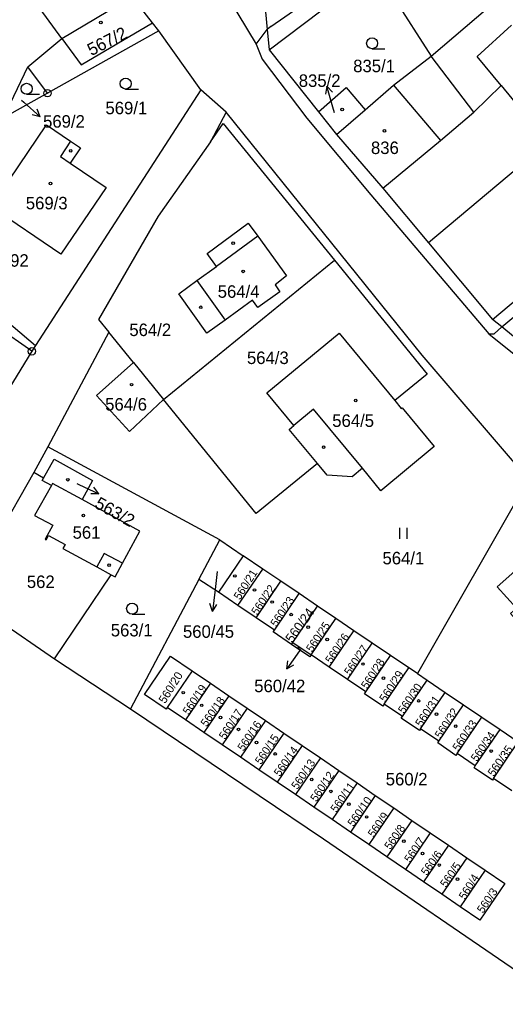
# Model space of a CAD drawing. Extents: x -776606 to -776076, y -974328 to -973875.
# Drawn here: x -776336.7 to -776270.5, y -974129.8 to -973997.7 of the extents above; entities that cross this region are included whole.
import ezdxf

# ---------------------------------------------------------------- set-up
doc = ezdxf.new("R2010")
doc.units = 0
for name, color, linetype in [('Hranice parcel', 7, 'Continuous'), ('Parcelní čísla', 7, 'Continuous'), ('Pop  PČ popisy', 7, 'Continuous'), ('Vnitřní kresba', 7, 'Continuous'), ('Značky bodu BP', 7, 'Continuous'), ('Značky budov', 7, 'Continuous'), ('Značky kultur', 7, 'Continuous')]:
    doc.layers.add(name, color=color, linetype=linetype)

msp = doc.modelspace()

# ---------------------------------------------------------------- linework, layer by layer
at = {"layer": 'Hranice parcel'}
for p, q in [((-776302.67, -974001.86), (-776288.2, -973990.91)), ((-776288.2, -973990.91), (-776280.61, -974002.73)), ((-776330.9, -974000.3), (-776321.3, -973994.6)), ((-776280.61, -974002.73), (-776271.38, -973994.77)), ((-776317.7, -973999.3), (-776332.85, -974007.77)), ((-776311.96, -974007.29), (-776317.7, -973999.3)), ((-776335.5, -974004.17), (-776330.9, -974000.3)), ((-776302.67, -974001.86), (-776295.97, -974010.29)), ((-776274.81, -974010.35), (-776280.61, -974002.73)), ((-776338.84, -974011.12), (-776335.5, -974004.17)), ((-776332.85, -974007.77), (-776335.5, -974004.17)), ((-776311.96, -974007.29), (-776334.46, -974042.11)), ((-776308.52, -974010.36), (-776311.96, -974007.29)), ((-776332.85, -974007.77), (-776338.84, -974011.12)), ((-776293.49, -974013.38), (-776289.58, -974010.03)), ((-776308.52, -974010.36), (-776310.67, -974014.4)), ((-776295.97, -974010.29), (-776293.49, -974013.38)), ((-776293.49, -974013.38), (-776287.2, -974020.7)), ((-776272.25, -974038.56), (-776255.71, -974024.55)), ((-776348.16, -974030.54), (-776334.46, -974042.11)), ((-776317.05, -974049.45), (-776293.78, -974030.52)), ((-776334.96, -974042.91), (-776348.94, -974033.12)), ((-776324.49, -974040.31), (-776332.81, -974055.91)), ((-776321.13, -974044.44), (-776324.49, -974040.31)), ((-776334.96, -974042.91), (-776338.11, -974048.02)), ((-776334.46, -974042.11), (-776334.96, -974042.91)), ((-776321.13, -974044.44), (-776317.05, -974049.45)), ((-776317.05, -974049.45), (-776321.68, -974053.83)), ((-776296.1, -974058.19), (-776299.93, -974053.54)), ((-776332.81, -974055.91), (-776334.7, -974059.4)), ((-776309.4, -974068.57), (-776332.81, -974055.91)), ((-776294.79, -974059.76), (-776296.1, -974058.19)), ((-776334.7, -974059.4), (-776344.3, -974076.22)), ((-776333.4, -974060.17), (-776334.7, -974059.4)), ((-776267.37, -974060.3), (-776282.47, -974086.79)), ((-776312.25, -974073.99), (-776309.4, -974068.57)), ((-776309.4, -974068.57), (-776306.21, -974070.73)), ((-776306.21, -974070.73), (-776309.57, -974075.7)), ((-776303.54, -974072.58), (-776306.21, -974070.73)), ((-776331.9, -974084.75), (-776324.18, -974073.32)), ((-776306.91, -974077.5), (-776303.54, -974072.58)), ((-776301.06, -974074.21), (-776303.54, -974072.58)), ((-776312.25, -974073.99), (-776321.52, -974091.59)), ((-776309.57, -974075.7), (-776312.25, -974073.99)), ((-776304.42, -974079.18), (-776301.06, -974074.21)), ((-776298.58, -974075.89), (-776301.06, -974074.21)), ((-776344.3, -974076.22), (-776331.9, -974084.75)), ((-776306.91, -974077.5), (-776309.57, -974075.7)), ((-776301.94, -974080.86), (-776298.58, -974075.89)), ((-776296.09, -974077.58), (-776298.58, -974075.89)), ((-776304.42, -974079.18), (-776306.91, -974077.5)), ((-776299.45, -974082.55), (-776296.09, -974077.58)), ((-776293.61, -974079.26), (-776296.09, -974077.58)), ((-776301.94, -974080.86), (-776304.42, -974079.18)), ((-776296.97, -974084.23), (-776293.61, -974079.26)), ((-776291.12, -974080.94), (-776293.61, -974079.26)), ((-776294.48, -974085.91), (-776291.12, -974080.94)), ((-776288.64, -974082.62), (-776291.12, -974080.94)), ((-776299.62, -974082.8), (-776299.45, -974082.55)), ((-776299.45, -974082.55), (-776296.97, -974084.23)), ((-776292, -974087.59), (-776288.64, -974082.62)), ((-776286.15, -974084.3), (-776288.64, -974082.62)), ((-776294.48, -974085.91), (-776296.97, -974084.23)), ((-776331.9, -974084.75), (-776321.52, -974091.59)), ((-776316.08, -974084.39), (-776313.14, -974086.4)), ((-776289.51, -974089.27), (-776286.15, -974084.3)), ((-776283.67, -974085.98), (-776286.15, -974084.3)), ((-776313.14, -974086.4), (-776316.53, -974091.38)), ((-776313.14, -974086.4), (-776310.65, -974088.1)), ((-776292, -974087.59), (-776294.48, -974085.91)), ((-776287.03, -974090.95), (-776283.67, -974085.98)), ((-776282.47, -974086.79), (-776283.67, -974085.98)), ((-776282.47, -974086.79), (-776281.18, -974087.66)), ((-776310.65, -974088.1), (-776314.04, -974093.08)), ((-776310.65, -974088.1), (-776308.15, -974089.79)), ((-776289.51, -974089.27), (-776292, -974087.59)), ((-776284.54, -974092.63), (-776281.18, -974087.66)), ((-776281.18, -974087.66), (-776278.7, -974089.35)), ((-776289.69, -974089.52), (-776289.51, -974089.27)), ((-776282.06, -974094.31), (-776278.7, -974089.35)), ((-776278.7, -974089.35), (-776276.21, -974091.03)), ((-776308.15, -974089.79), (-776311.55, -974094.78)), ((-776308.15, -974089.79), (-776305.66, -974091.49)), ((-776287.2, -974091.2), (-776289.69, -974089.52)), ((-776316.53, -974091.38), (-776316.69, -974091.62)), ((-776314.04, -974093.08), (-776316.53, -974091.38)), ((-776305.66, -974091.49), (-776309.05, -974096.47)), ((-776305.66, -974091.49), (-776303.17, -974093.18)), ((-776287.03, -974090.95), (-776287.2, -974091.2)), ((-776284.54, -974092.63), (-776287.03, -974090.95)), ((-776279.58, -974096), (-776276.21, -974091.03)), ((-776276.21, -974091.03), (-776273.73, -974092.71)), ((-776311.55, -974094.78), (-776314.04, -974093.08)), ((-776303.17, -974093.18), (-776306.56, -974098.17)), ((-776303.17, -974093.18), (-776300.68, -974094.88)), ((-776284.7, -974092.87), (-776284.54, -974092.63)), ((-776282.22, -974094.54), (-776284.7, -974092.87)), ((-776277.09, -974097.68), (-776273.73, -974092.71)), ((-776273.73, -974092.71), (-776271.24, -974094.39)), ((-776309.05, -974096.47), (-776311.55, -974094.78)), ((-776282.06, -974094.31), (-776282.22, -974094.54)), ((-776279.58, -974096), (-776282.06, -974094.31)), ((-776274.61, -974099.36), (-776271.24, -974094.39)), ((-776271.24, -974094.39), (-776268.76, -974096.07)), ((-776300.68, -974094.88), (-776304.07, -974099.87)), ((-776300.68, -974094.88), (-776298.19, -974096.58)), ((-776279.73, -974096.22), (-776279.58, -974096)), ((-776272.12, -974101.04), (-776268.76, -974096.07)), ((-776306.56, -974098.17), (-776309.05, -974096.47)), ((-776298.19, -974096.58), (-776301.58, -974101.56)), ((-776298.19, -974096.58), (-776295.69, -974098.27)), ((-776277.25, -974097.91), (-776279.73, -974096.22)), ((-776304.07, -974099.87), (-776306.56, -974098.17)), ((-776295.69, -974098.27), (-776299.09, -974103.26)), ((-776295.69, -974098.27), (-776293.2, -974099.97)), ((-776277.09, -974097.68), (-776277.25, -974097.91)), ((-776274.61, -974099.36), (-776277.09, -974097.68)), ((-776301.58, -974101.56), (-776304.07, -974099.87)), ((-776293.2, -974099.97), (-776296.59, -974104.95)), ((-776293.2, -974099.97), (-776290.71, -974101.67)), ((-776274.77, -974099.61), (-776274.61, -974099.36)), ((-776272.29, -974101.29), (-776274.77, -974099.61)), ((-776272.12, -974101.04), (-776272.29, -974101.29)), ((-776269.64, -974102.72), (-776272.12, -974101.04)), ((-776299.09, -974103.26), (-776301.58, -974101.56)), ((-776290.71, -974101.67), (-776294.1, -974106.65)), ((-776290.71, -974101.67), (-776288.22, -974103.36)), ((-776296.59, -974104.95), (-776299.09, -974103.26)), ((-776288.22, -974103.36), (-776291.61, -974108.35)), ((-776288.22, -974103.36), (-776285.72, -974105.06)), ((-776294.1, -974106.65), (-776296.59, -974104.95)), ((-776285.72, -974105.06), (-776289.12, -974110.04)), ((-776285.72, -974105.06), (-776283.23, -974106.76)), ((-776291.61, -974108.35), (-776294.1, -974106.65)), ((-776283.23, -974106.76), (-776286.63, -974111.74)), ((-776283.23, -974106.76), (-776280.74, -974108.45)), ((-776289.12, -974110.04), (-776291.61, -974108.35)), ((-776280.74, -974108.45), (-776284.13, -974113.44)), ((-776280.74, -974108.45), (-776278.25, -974110.15)), ((-776286.63, -974111.74), (-776289.12, -974110.04)), ((-776278.25, -974110.15), (-776281.64, -974115.13)), ((-776278.25, -974110.15), (-776275.76, -974111.85)), ((-776284.13, -974113.44), (-776286.63, -974111.74)), ((-776275.76, -974111.85), (-776279.15, -974116.83)), ((-776275.76, -974111.85), (-776273.26, -974113.54)), ((-776281.64, -974115.13), (-776284.13, -974113.44)), ((-776273.26, -974113.54), (-776276.66, -974118.53)), ((-776279.15, -974116.83), (-776281.64, -974115.13)), ((-776276.66, -974118.53), (-776279.15, -974116.83))]:
    msp.add_line(p, q, dxfattribs=at)
for points in [[(-776348.8, -973929.48), (-776343.01, -973940.47), (-776336.28, -973951.4), (-776326.2, -973966.93), (-776309.58, -973992.58), (-776304.42, -974001.08), (-776303.62, -974003.12), (-776297.56, -974011.17), (-776288.84, -974021.6), (-776272.77, -974040.55), (-776267.29, -974044.95), (-776253.84, -974055.49), (-776252.47, -974056.28)], [(-776303.87, -973989.21), (-776303.72, -973990.83), (-776302.93, -973999.08), (-776302.67, -974001.86)], [(-776330.9, -974000.3), (-776334.7, -973995.1), (-776335.9, -973995.95), (-776336.89, -973994.45)], [(-776317.7, -973999.3), (-776318.56, -973998.17), (-776321.3, -973994.6)], [(-776289.58, -974010.03), (-776285.74, -974006.66), (-776280.61, -974002.73)], [(-776295.97, -974010.29), (-776292.19, -974007.01), (-776289.58, -974010.03)], [(-776274.81, -974010.35), (-776271.09, -974006.74), (-776266.72, -974012.05)], [(-776267.37, -974060.3), (-776281.86, -974043.45), (-776308.52, -974010.36)], [(-776287.2, -974020.7), (-776279.35, -974014.2), (-776274.81, -974010.35)], [(-776340.54, -974023.25), (-776332.99, -974012.08), (-776329.69, -974014.3), (-776328.36, -974015.19), (-776329.75, -974017.28), (-776324.86, -974020.59), (-776331.02, -974029.69), (-776340.54, -974023.25)], [(-776310.67, -974014.4), (-776308.92, -974011.9), (-776293.78, -974030.52)], [(-776310.67, -974014.4), (-776317.77, -974024.51), (-776325.89, -974038.59), (-776324.49, -974040.31)], [(-776287.2, -974020.7), (-776280.99, -974028.12), (-776272.25, -974038.56)], [(-776300.3, -974032.65), (-776301.87, -974033.84), (-776301.2, -974034.79), (-776304.23, -974036.93), (-776304.95, -974035.94), (-776308.67, -974038.65), (-776311.16, -974040.45), (-776314.95, -974035.08), (-776312.51, -974033.28), (-776309.82, -974031.36), (-776311.09, -974029.58), (-776305.51, -974025.48), (-776304.23, -974027.24), (-776300.3, -974032.65)], [(-776293.78, -974030.52), (-776281.16, -974046.04), (-776285.56, -974049.62)], [(-776266.49, -974043.3), (-776270.99, -974039.59), (-776272.25, -974038.56)], [(-776299.93, -974053.54), (-776299.29, -974053.02), (-776302.98, -974048.54), (-776293.15, -974040.43), (-776285.56, -974049.62)], [(-776321.68, -974053.83), (-776326.17, -974048.92), (-776321.13, -974044.44)], [(-776296.1, -974058.19), (-776304.44, -974064.97), (-776317.05, -974049.45)], [(-776285.56, -974049.62), (-776284.68, -974050.68), (-776284.56, -974050.58), (-776280.21, -974055.85), (-776287.46, -974061.89), (-776289.98, -974058.83), (-776291.39, -974059.99), (-776294.79, -974059.76)], [(-776333.4, -974060.17), (-776331.95, -974057.57), (-776326.69, -974060.51), (-776328.13, -974063.09)], [(-776332.31, -974061.19), (-776333.57, -974060.48), (-776333.4, -974060.17)], [(-776332.31, -974061.19), (-776334.6, -974065.25), (-776332.13, -974066.56)], [(-776328.13, -974063.09), (-776332.15, -974060.9), (-776332.31, -974061.19)], [(-776322.64, -974071.77), (-776320.25, -974067.39), (-776328.13, -974063.09)], [(-776332.13, -974066.56), (-776333.16, -974068.48), (-776333.02, -974068.55), (-776332.71, -974067.97), (-776330.45, -974069.2), (-776330.74, -974069.73), (-776326.12, -974072.26), (-776324.18, -974073.32)], [(-776266.42, -974070.32), (-776263.79, -974073.24), (-776263.01, -974072.55), (-776256.77, -974079.49), (-776263.55, -974085.59), (-776269.82, -974078.62), (-776268.99, -974077.88), (-776271.61, -974074.97), (-776266.42, -974070.32)], [(-776324.18, -974073.32), (-776323.64, -974073.61), (-776322.64, -974071.77)], [(-776299.62, -974082.8), (-776302.11, -974081.11), (-776301.94, -974080.86)], [(-776296.97, -974084.23), (-776297.14, -974084.48), (-776299.62, -974082.8)], [(-776316.69, -974091.62), (-776319.62, -974089.62), (-776316.08, -974084.39)], [(-776321.52, -974091.59), (-776295.28, -974109.27), (-776265.27, -974129.8)], [(-776273.26, -974113.54), (-776270.58, -974115.37), (-776273.97, -974120.35), (-776276.66, -974118.53)]]:
    msp.add_lwpolyline(points, dxfattribs=at)
at = {"layer": 'Pop  PČ popisy'}
for p, q in [((-776294.81, -974006.81), (-776295.01, -974007.91)), ((-776293.98, -974009.69), (-776294.81, -974006.81)), ((-776294.81, -974006.81), (-776294.05, -974007.63)), ((-776336.36, -974008.73), (-776336.07, -974008.99)), ((-776336.07, -974008.99), (-776333.84, -974011)), ((-776333.84, -974011), (-776334.25, -974009.96)), ((-776293.76, -974010.45), (-776293.98, -974009.69)), ((-776333.84, -974011), (-776334.92, -974010.7)), ((-776328.86, -974060.89), (-776328.56, -974061.03)), ((-776328.56, -974061.03), (-776325.84, -974062.3)), ((-776325.84, -974062.3), (-776326.54, -974061.42)), ((-776325.84, -974062.3), (-776326.96, -974062.33)), ((-776309.75, -974072.9), (-776310.02, -974075.34)), ((-776310.02, -974075.34), (-776310.39, -974078.32)), ((-776310.39, -974078.32), (-776310.76, -974077.26)), ((-776310.39, -974078.32), (-776309.77, -974077.39)), ((-776298.56, -974083.68), (-776300.28, -974086.14)), ((-776298.4, -974083.45), (-776298.56, -974083.68)), ((-776300.28, -974086.14), (-776300.12, -974085.03)), ((-776300.28, -974086.14), (-776299.3, -974085.6))]:
    msp.add_line(p, q, dxfattribs=at)
at = {"layer": 'Vnitřní kresba'}
for p, q in [((-776302.45, -973998.67), (-776260.07, -973969.53)), ((-776328.24, -974003.93), (-776318.56, -973998.17)), ((-776304.42, -974001.08), (-776302.93, -973999.08)), ((-776302.45, -973998.67), (-776302.93, -973999.08)), ((-776274.36, -974002.77), (-776269.67, -973998.49)), ((-776330.9, -974000.3), (-776328.24, -974003.93)), ((-776271.09, -974006.74), (-776274.36, -974002.77)), ((-776285.74, -974006.66), (-776279.35, -974014.2)), ((-776264.63, -974014.42), (-776280.99, -974028.12)), ((-776270.99, -974039.59), (-776254.65, -974025.76)), ((-776304.23, -974027.24), (-776309.82, -974031.36)), ((-776312.51, -974033.28), (-776308.67, -974038.65)), ((-776296.61, -974050.8), (-776299.29, -974053.02)), ((-776289.98, -974058.83), (-776296.61, -974050.8)), ((-776325.11, -974070.42), (-776326.12, -974072.26)), ((-776322.64, -974071.77), (-776325.11, -974070.42))]:
    msp.add_line(p, q, dxfattribs=at)
for points in [[(-776329.69, -974014.3), (-776331.09, -974016.37), (-776329.75, -974017.28)], [(-776272.77, -974040.55), (-776272.06, -974040.55), (-776270.99, -974039.59)]]:
    msp.add_lwpolyline(points, dxfattribs=at)
at = {"layer": 'Značky bodu BP'}
for centre, radius in [((-776332.85, -974007.77), 0.5), ((-776332.85, -974007.77), 0.0303), ((-776334.96, -974042.91), 0.5), ((-776334.96, -974042.91), 0.0303)]:
    msp.add_circle(centre, radius, dxfattribs=at)
at = {"layer": 'Značky budov'}
for centre, radius in [((-776325.58, -973998.14), 0.175), ((-776292.73, -974009.99), 0.175), ((-776286.98, -974012.89), 0.175), ((-776329.68, -974015.61), 0.175), ((-776332.42, -974020.07), 0.175), ((-776307.57, -974028.19), 0.175), ((-776306.21, -974032.03), 0.175), ((-776311.98, -974036.91), 0.175), ((-776321.39, -974047.45), 0.175), ((-776290.89, -974049.6), 0.175), ((-776295.25, -974055.96), 0.175), ((-776330.06, -974060.39), 0.175), ((-776327.96, -974065.26), 0.175), ((-776324.46, -974072.03), 0.175), ((-776307.33, -974073.49), 0.175), ((-776304.67, -974075.4), 0.175), ((-776302.25, -974077.04), 0.175), ((-776299.67, -974078.75), 0.175), ((-776297.35, -974080.46), 0.175), ((-776294.77, -974082.14), 0.175), ((-776298.65, -974083.28), 0.117), ((-776289.9, -974085.48), 0.175), ((-776287.12, -974087.41), 0.175), ((-776314.36, -974089.38), 0.175), ((-776282.32, -974090.5), 0.175), ((-776311.85, -974091.1), 0.175), ((-776279.88, -974092.31), 0.175), ((-776309.29, -974092.75), 0.175), ((-776306.84, -974094.38), 0.175), ((-776277.28, -974093.93), 0.175), ((-776304.38, -974096.16), 0.175), ((-776272.44, -974097.33), 0.175), ((-776301.85, -974097.72), 0.175), ((-776296.88, -974101.19), 0.175), ((-776294.26, -974102.82), 0.175), ((-776291.82, -974104.56), 0.175), ((-776289.4, -974106.3), 0.175), ((-776284.33, -974109.59), 0.175), ((-776281.78, -974111.28), 0.175), ((-776279.51, -974112.85), 0.175), ((-776277.03, -974114.77), 0.175)]:
    msp.add_circle(centre, radius, dxfattribs=at)
at = {"layer": 'Značky kultur'}
for p, q in [((-776288.65, -974001.72), (-776286.9, -974001.72)), ((-776322.2, -974007.21), (-776320.45, -974007.21)), ((-776335.68, -974007.92), (-776333.93, -974007.92)), ((-776284.89, -974068.45), (-776284.89, -974066.95)), ((-776283.89, -974068.45), (-776283.89, -974066.95)), ((-776321.32, -974078.69), (-776319.57, -974078.69))]:
    msp.add_line(p, q, dxfattribs=at)
for centre in [(-776288.65, -974000.97), (-776322.2, -974006.46), (-776335.68, -974007.17), (-776321.32, -974077.94)]:
    msp.add_circle(centre, 0.75, dxfattribs=at)

# ---------------------------------------------------------------- texts
at = {"layer": 'Parcelní čísla'}
for s, height, rotation, p in [('567/2', 1.7, 27, (-776326.87, -974002.74)), ('563/2', 1.7, 331, (-776326.56, -974064.12)), ('560/21', 1.1, 57, (-776306.65, -974076.83)), ('560/22', 1.1, 56, (-776304.28, -974078.9)), ('560/23', 1.1, 56, (-776301.68, -974080.51)), ('560/24', 1.282, 54, (-776299.53, -974082.7)), ('560/25', 1.1, 56, (-776296.82, -974083.95)), ('560/26', 1.1, 56, (-776294.21, -974085.5)), ('560/27', 1.1, 56, (-776291.64, -974087.11)), ('560/28', 1.1, 57, (-776289.32, -974088.96)), ('560/20', 1.139, 58, (-776316.83, -974090.95)), ('560/29', 1.139, 57, (-776286.81, -974090.76)), ('560/30', 1.1, 56, (-776284.31, -974092.32)), ('560/19', 1.1, 56, (-776313.62, -974092.48)), ('560/18', 1.1, 55, (-776311.19, -974094.11)), ('560/31', 1.139, 56, (-776281.93, -974094.14)), ('560/17', 1.1, 57, (-776308.67, -974095.85)), ('560/32', 1.1, 57, (-776279.29, -974095.71)), ('560/16', 1.1, 56, (-776306.16, -974097.42)), ('560/33', 1.139, 56, (-776276.87, -974097.45)), ('560/34', 1.1, 55, (-776274.41, -974098.86)), ('560/15', 1.1, 56, (-776303.78, -974099.25)), ('560/14', 1.1, 55, (-776301.22, -974100.88)), ('560/35', 1.139, 55, (-776272.09, -974100.89)), ('560/13', 1.1, 56, (-776298.83, -974102.64)), ('560/12', 1.1, 56, (-776296.25, -974104.32)), ('560/11', 1.1, 55, (-776293.51, -974105.77)), ('560/10', 1.1, 55, (-776291.19, -974107.71)), ('560/9', 1.1, 55, (-776288.43, -974109.16)), ('560/8', 1.1, 55, (-776286.18, -974110.84)), ('560/7', 1.1, 56, (-776283.46, -974112.6)), ('560/6', 1.1, 54, (-776281.22, -974114.36)), ('560/5', 1.1, 55, (-776278.59, -974115.98)), ('560/4', 1.1, 58, (-776276, -974117.65)), ('560/3', 1.1, 56, (-776273.56, -974119.5))]:
    msp.add_text(s, height=height, rotation=rotation, dxfattribs=at).set_placement(p)
for s, p in [('835/1', (-776291.23, -974004.91)), ('835/2', (-776298.64, -974006.91)), ('569/1', (-776324.95, -974010.63)), ('569/2', (-776333.44, -974012.46)), ('836', (-776288.81, -974016.05)), ('569/3', (-776335.79, -974023.58)), ('573/92', (-776342.35, -974031.39)), ('564/4', (-776309.67, -974035.62)), ('564/2', (-776321.7, -974040.83)), ('564/3', (-776305.69, -974044.64)), ('564/6', (-776324.99, -974050.97)), ('564/5', (-776294.08, -974053.2)), ('561', (-776329.42, -974068.42)), ('564/1', (-776287.24, -974071.91)), ('562', (-776335.65, -974075.13)), ('563/1', (-776324.22, -974081.72)), ('560/45', (-776314.4, -974081.91)), ('560/42', (-776304.7, -974089.31)), ('560/2', (-776286.8, -974102))]:
    msp.add_text(s, height=1.7, dxfattribs=at).set_placement(p)

doc.saveas('drawing.dxf')
